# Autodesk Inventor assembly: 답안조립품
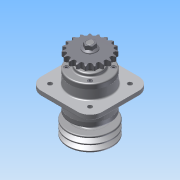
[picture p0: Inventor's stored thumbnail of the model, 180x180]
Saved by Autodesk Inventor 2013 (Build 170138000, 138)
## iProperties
Created: 2015-09
Part Number: 답안조립품
Document SubType Name: Assembly
Designer: dfdfd
Author: dfdfd
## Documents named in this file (12)
- C:\Users\dfdfd\Desktop\450909V1014\답안조립품.iam
- C:\Users\dfdfd\Desktop\450909V1014\1-본체.ipt
- C:\Users\dfdfd\Desktop\450909V1014\2-커버.ipt
- C:\Users\dfdfd\Desktop\450909V1014\6-베어링 6206.ipt
- C:\Users\dfdfd\Desktop\450909V1014\8-오일실 30x42.ipt
- C:\Users\dfdfd\Desktop\450909V1014\9-M16-너트.ipt
- C:\Users\dfdfd\Desktop\450909V1014\11-키 6x6.ipt
- C:\Users\dfdfd\Desktop\450909V1014\3-축.ipt
- C:\Users\dfdfd\Desktop\450909V1014\4-V벨트풀리.ipt
- C:\Users\dfdfd\Desktop\450909V1014\5-체인 스프로킷.ipt
- C:\Users\dfdfd\Desktop\450909V1014\7-부시.ipt
- C:\Users\dfdfd\Desktop\450909V1014\10-M6.ipt
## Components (23 placed, 11 different names)
1. 1-본체:1
2. 2-커버:1
3. 6-베어링 6206:1
4. 8-8-오일실 30x42:1
5. 9-M16 너트:1 — 각도:5
6. 11-키 6x6:1 — 각도:2, 각도:4
7. 2-커버:2
8. 6-베어링 6206:2
9. 8-8-오일실 30x42:2
10. 9-M16 너트:2 — 각도:6
11. 11-키 6x6:2 — 각도:1, 각도:3
12. 3-축:1 — 각도:1, 각도:2, 각도:5, 각도:6
13. 4-V벨트풀리:1 — 각도:3
14. 5-체인 스프로킷:1 — 각도:4
15. 7-부시:1
16. 10-M6:1
17. 10-M6:3
18. 10-M6:4
19. 10-M6:5
20. 10-M6:2
21. 10-M6:6
22. 10-M6:7
23. 10-M6:8
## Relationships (6: Angle 6)
- 각도:1 [Angle]: 11-키 6x6:2 ↔ 3-축:1
- 각도:2 [Angle]: 11-키 6x6:1 ↔ 3-축:1
- 각도:3 [Angle]: 11-키 6x6:2 ↔ 4-V벨트풀리:1
- 각도:4 [Angle]: 11-키 6x6:1 ↔ 5-체인 스프로킷:1
- 각도:5 [Angle]: 9-M16 너트:1 ↔ 3-축:1
- 각도:6 [Angle]: 9-M16 너트:2 ↔ 3-축:1
